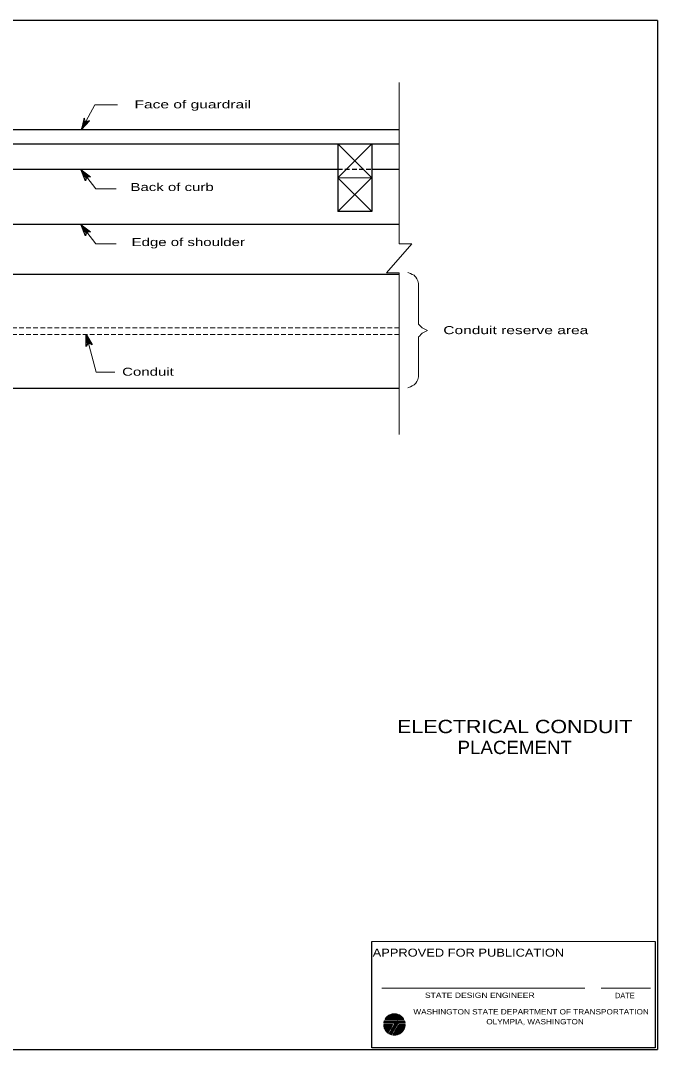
# Model space of a CAD drawing. Extents: x 993470 to 994006, y 1010815 to 1011161.
# Drawn here: x 993791.1 to 994005.6, y 1010814.9 to 1011161.5 of the extents above; entities that cross this region are included whole.
import ezdxf
from ezdxf.enums import TextEntityAlignment as Align

# ---------------------------------------------------------------- set-up
doc = ezdxf.new("R2010")
doc.units = 0
doc.header["$LTSCALE"] = 0.53
doc.linetypes.add('LONG_DASHED', pattern=[7.5, 6, -1.5])
doc.linetypes.add('MEDIUM_DASHED', pattern=[4.5, 3, -1.5])
for name, color, linetype, lineweight in [('1', 7, 'Continuous', 25), ('15', 7, 'Continuous', 13), ('16', 7, 'Continuous', 25), ('20', 7, 'Continuous', 13), ('30', 7, 'Continuous', 25), ('32', 7, 'Continuous', 25), ('63', 7, 'Continuous', 13)]:
    doc.layers.add(name, color=color, linetype=linetype, lineweight=lineweight)

msp = doc.modelspace()

# ---------------------------------------------------------------- linework, layer by layer
at = {"layer": '1'}
for p, q in [((993897.987, 1011119.934), (993897.987, 1011097.116)), ((993909.389, 1011119.934), (993909.389, 1011097.116)), ((993509.149, 1011076.054), (993918.64, 1011076.054))]:
    msp.add_line(p, q, dxfattribs=at)
at = {"layer": '1', "linetype": 'MEDIUM_DASHED', "lineweight": 13}
for p, q in [((993918.64, 1011058.023), (993727.094, 1011058.023)), ((993918.64, 1011055.697), (993727.094, 1011055.697))]:
    msp.add_line(p, q, dxfattribs=at)
at = {"layer": '1', "lineweight": 13}
for p, q in [((993909.389, 1010851.248), (994004.853, 1010851.248)), ((993912.843, 1010835.566), (993981.209, 1010835.566)), ((993986.617, 1010835.566), (994003.227, 1010835.566))]:
    msp.add_line(p, q, dxfattribs=at)
at = {"layer": '15'}
msp.add_lwpolyline([(993918.64, 1011086.217), (993922.874, 1011086.217), (993914.407, 1011076.455), (993918.64, 1011076.455)], dxfattribs=at)
at = {"layer": '15', "lineweight": 25}
msp.add_lwpolyline([(994004.853, 1010851.248), (994004.853, 1010815.474), (993909.389, 1010815.474), (993909.389, 1010851.248)], dxfattribs=at)
at = {"layer": '16'}
for points in [[(993812.819, 1011127.826), (993812.561, 1011128.654), (993811.649, 1011124.772), (993814.403, 1011127.654), (993813.575, 1011127.426), (993811.649, 1011124.772), (993812.819, 1011127.826), (993812.989, 1011127.254), (993813.575, 1011127.426)], [(993813.181, 1011108.364), (993813.053, 1011107.506), (993811.527, 1011111.188), (993814.709, 1011108.792), (993813.853, 1011108.892), (993811.527, 1011111.188), (993813.181, 1011108.364), (993813.253, 1011108.962), (993813.853, 1011108.892)], [(993813.181, 1011089.826), (993813.053, 1011088.968), (993811.527, 1011092.65), (993814.709, 1011090.254), (993813.853, 1011090.354), (993811.527, 1011092.65), (993813.181, 1011089.826), (993813.253, 1011090.424), (993813.853, 1011090.354)], [(993813.693, 1011052.443), (993813.235, 1011051.717), (993813.265, 1011055.697), (993815.263, 1011052.245), (993814.505, 1011052.673), (993813.265, 1011055.697), (993813.693, 1011052.443), (993813.993, 1011052.971), (993814.505, 1011052.673)]]:
    msp.add_lwpolyline(points, dxfattribs=at)
at = {"layer": '20'}
msp.add_lwpolyline([(993921.52, 1011076.579), (993922.44, 1011076.277), (993923.044, 1011075.975), (993923.662, 1011075.659), (993923.964, 1011075.357), (993924.266, 1011075.055), (993924.568, 1011074.437), (993924.884, 1011073.833), (993925.186, 1011072.913), (993925.186, 1011059.183), (993925.79, 1011058.564), (993926.408, 1011057.96), (993927.012, 1011057.644), (993928.234, 1011057.04), (993926.408, 1011056.12), (993926.092, 1011055.818), (993925.488, 1011055.2), (993925.186, 1011054.898), (993925.186, 1011041.47), (993924.884, 1011040.55), (993924.568, 1011039.946), (993924.266, 1011039.328), (993923.964, 1011039.026), (993923.662, 1011038.724), (993923.044, 1011038.408), (993922.44, 1011038.106), (993921.52, 1011037.804)], dxfattribs=at)
at = {"layer": '30'}
for p, q in [((994005.609, 1011161.474), (993469.979, 1011161.474)), ((994005.609, 1011161.474), (994005.609, 1010814.89)), ((993469.979, 1010814.89), (994005.609, 1010814.89))]:
    msp.add_line(p, q, dxfattribs=at)
at = {"layer": '32', "lineweight": 13}
for p, q in [((993918.64, 1011086.217), (993918.64, 1011140.582)), ((993897.987, 1011119.934), (993909.389, 1011108.504)), ((993898.001, 1011108.532), (993909.389, 1011119.934)), ((993816.479, 1011104.838), (993811.527, 1011111.188)), ((993909.375, 1011108.532), (993897.987, 1011108.546)), ((993897.987, 1011108.546), (993909.389, 1011097.116)), ((993897.987, 1011097.116), (993909.375, 1011108.532)), ((993816.479, 1011104.838), (993823.313, 1011104.838)), ((993816.479, 1011086.3), (993811.527, 1011092.65)), ((993816.479, 1011086.3), (993823.313, 1011086.3)), ((993918.64, 1011022.09), (993918.64, 1011076.455)), ((993816.646, 1011043.015), (993813.265, 1011055.697)), ((993816.646, 1011043.015), (993822.826, 1011043.015))]:
    msp.add_line(p, q, dxfattribs=at)
at = {"layer": '32'}
for p, q in [((993509.149, 1011124.772), (993918.64, 1011124.772)), ((993509.149, 1011119.934), (993918.64, 1011119.934)), ((993785.783, 1011111.458), (993897.987, 1011111.458)), ((993909.389, 1011111.458), (993918.64, 1011111.458)), ((993909.389, 1011097.116), (993897.987, 1011097.116)), ((993509.149, 1011092.92), (993918.64, 1011092.92)), ((993509.149, 1011037.654), (993918.64, 1011037.654))]:
    msp.add_line(p, q, dxfattribs=at)
at = {"layer": '32', "linetype": 'LONG_DASHED', "lineweight": 13}
msp.add_line((993909.389, 1011119.934), (993897.987, 1011119.934), dxfattribs=at)
at = {"layer": '32', "linetype": 'MEDIUM_DASHED'}
msp.add_line((993897.987, 1011111.458), (993909.389, 1011111.458), dxfattribs=at)
at = {"layer": '32', "lineweight": 13}
msp.add_lwpolyline([(993823.777, 1011133.062), (993816.143, 1011133.062), (993811.649, 1011124.772)], dxfattribs=at)
at = {"layer": '63'}
for points in [[(993920.191, 1010825.02), (993913.869, 1010825.02), (993913.927, 1010825.092), (993920.149, 1010825.092), (993920.091, 1010825.192), (993913.983, 1010825.192), (993914.027, 1010825.278), (993920.035, 1010825.278), (993919.991, 1010825.378), (993914.083, 1010825.378), (993914.141, 1010825.448), (993919.935, 1010825.448), (993919.849, 1010825.534), (993914.197, 1010825.534), (993914.283, 1010825.606), (993919.791, 1010825.606), (993919.691, 1010825.706), (993914.383, 1010825.706), (993914.427, 1010825.806), (993919.635, 1010825.806), (993919.535, 1010825.892), (993914.525, 1010825.892), (993914.611, 1010825.962), (993919.449, 1010825.962), (993919.363, 1010826.048), (993914.711, 1010826.048), (993914.811, 1010826.148), (993919.249, 1010826.148), (993919.149, 1010826.22), (993914.925, 1010826.22), (993915.069, 1010826.32), (993919.007, 1010826.32), (993918.863, 1010826.39), (993915.211, 1010826.39), (993915.367, 1010826.49), (993918.707, 1010826.49), (993918.535, 1010826.562), (993915.539, 1010826.562), (993915.739, 1010826.648), (993918.335, 1010826.648), (993918.079, 1010826.748), (993915.995, 1010826.748), (993916.323, 1010826.832), (993917.751, 1010826.832), (993917.565, 1010826.848), (993917.337, 1010826.89), (993917.037, 1010826.89), (993916.737, 1010826.89), (993916.495, 1010826.848), (993916.323, 1010826.832)], [(993913.927, 1010825.092), (993913.983, 1010825.192), (993914.027, 1010825.278), (993914.083, 1010825.378), (993914.141, 1010825.448), (993914.197, 1010825.534), (993914.283, 1010825.606), (993914.383, 1010825.706), (993914.427, 1010825.806), (993914.525, 1010825.892), (993914.611, 1010825.962), (993914.711, 1010826.048), (993914.811, 1010826.148), (993914.925, 1010826.22), (993915.069, 1010826.32), (993915.211, 1010826.39), (993915.367, 1010826.49), (993915.539, 1010826.562), (993915.739, 1010826.648), (993915.995, 1010826.748)], [(993917.751, 1010826.832), (993918.079, 1010826.748), (993918.335, 1010826.648), (993918.535, 1010826.562), (993918.707, 1010826.49), (993918.863, 1010826.39), (993919.007, 1010826.32), (993919.149, 1010826.22), (993919.249, 1010826.148), (993919.363, 1010826.048), (993919.449, 1010825.962), (993919.535, 1010825.892), (993919.635, 1010825.806), (993919.691, 1010825.706), (993919.791, 1010825.606), (993919.849, 1010825.534), (993919.935, 1010825.448), (993919.991, 1010825.378), (993920.035, 1010825.278), (993920.091, 1010825.192), (993920.149, 1010825.092), (993920.191, 1010825.02)], [(993913.469, 1010823.95), (993920.591, 1010823.95), (993920.605, 1010823.85), (993913.469, 1010823.85), (993913.441, 1010823.78), (993920.605, 1010823.78), (993918.707, 1010823.78), (993918.621, 1010823.736), (993918.421, 1010823.68), (993917.081, 1010823.68), (993917.137, 1010823.594), (993918.265, 1010823.594), (993918.165, 1010823.536), (993918.137, 1010823.508), (993917.137, 1010823.508), (993917.137, 1010823.48), (993917.123, 1010823.422), (993918.065, 1010823.422), (993918.023, 1010823.366), (993917.979, 1010823.352), (993917.037, 1010823.352), (993916.995, 1010823.252), (993917.951, 1010823.252), (993917.907, 1010823.166), (993916.967, 1010823.166), (993916.895, 1010823.066), (993917.851, 1010823.066), (993917.807, 1010822.994), (993916.837, 1010822.994), (993916.781, 1010822.894), (993917.751, 1010822.894), (993917.693, 1010822.838), (993916.737, 1010822.838), (993916.709, 1010822.738), (993917.651, 1010822.738), (993917.609, 1010822.652), (993916.667, 1010822.652), (993916.581, 1010822.552), (993917.537, 1010822.552), (993917.495, 1010822.452), (993916.553, 1010822.452), (993916.509, 1010822.38), (993917.451, 1010822.38), (993917.395, 1010822.296), (993916.453, 1010822.296), (993916.395, 1010822.224), (993917.351, 1010822.224), (993917.295, 1010822.124), (993916.353, 1010822.124), (993916.295, 1010822.038), (993917.237, 1010822.038), (993917.195, 1010821.952), (993916.253, 1010821.952), (993916.209, 1010821.868), (993917.151, 1010821.868), (993917.081, 1010821.796), (993916.153, 1010821.796), (993916.095, 1010821.71), (993917.037, 1010821.71), (993916.995, 1010821.61), (993916.053, 1010821.61), (993915.995, 1010821.538), (993916.937, 1010821.538), (993916.895, 1010821.438), (993915.953, 1010821.438), (993915.895, 1010821.354), (993916.837, 1010821.34), (993916.781, 1010821.254), (993915.853, 1010821.254), (993915.795, 1010821.182), (993916.737, 1010821.182), (993916.709, 1010821.096), (993915.739, 1010821.096), (993915.697, 1010820.996), (993916.653, 1010820.996), (993916.581, 1010820.926), (993915.667, 1010820.926), (993915.597, 1010820.826), (993916.553, 1010820.826), (993916.495, 1010820.74), (993915.567, 1010820.74), (993915.511, 1010820.668), (993916.453, 1010820.668), (993916.395, 1010820.582), (993915.439, 1010820.582), (993915.411, 1010820.482), (993916.353, 1010820.482), (993916.295, 1010820.412), (993915.325, 1010820.412), (993915.283, 1010820.312), (993916.253, 1010820.312), (993916.195, 1010820.24), (993915.253, 1010820.24), (993915.211, 1010820.198), (993915.311, 1010820.14), (993916.153, 1010820.14), (993916.095, 1010820.054), (993915.511, 1010820.054), (993915.667, 1010819.954), (993916.053, 1010819.954), (993915.995, 1010819.884)], [(993913.441, 1010823.308), (993916.295, 1010823.308), (993916.367, 1010823.28), (993916.395, 1010823.252), (993916.409, 1010823.208), (993913.441, 1010823.208), (993913.441, 1010823.108), (993916.409, 1010823.108), (993916.367, 1010823.022), (993913.441, 1010823.022), (993913.441, 1010822.952), (993916.323, 1010822.952), (993916.295, 1010822.866), (993913.469, 1010822.866), (993913.469, 1010822.78), (993916.239, 1010822.78), (993916.167, 1010822.694), (993913.499, 1010822.694), (993913.513, 1010822.624), (993916.109, 1010822.624), (993916.081, 1010822.524), (993913.541, 1010822.524), (993913.541, 1010822.438), (993916.039, 1010822.438), (993915.953, 1010822.338), (993913.555, 1010822.338), (993913.599, 1010822.28), (993915.911, 1010822.28), (993915.881, 1010822.18), (993913.613, 1010822.18), (993913.627, 1010822.082), (993915.839, 1010822.082), (993915.781, 1010821.982), (993913.669, 1010821.982), (993913.713, 1010821.91), (993915.725, 1010821.924), (993915.667, 1010821.824), (993913.755, 1010821.824), (993913.783, 1010821.752), (993915.625, 1010821.752), (993915.581, 1010821.652), (993913.827, 1010821.652), (993913.869, 1010821.568), (993915.511, 1010821.568), (993915.467, 1010821.496), (993913.927, 1010821.496), (993913.983, 1010821.396), (993915.425, 1010821.396), (993915.367, 1010821.31), (993914.027, 1010821.31), (993914.083, 1010821.24), (993915.325, 1010821.24), (993915.267, 1010821.14), (993914.141, 1010821.14), (993914.227, 1010821.04), (993915.211, 1010821.04), (993915.169, 1010820.968), (993914.297, 1010820.968), (993914.383, 1010820.868), (993915.111, 1010820.868), (993915.069, 1010820.812), (993914.455, 1010820.812), (993914.541, 1010820.712), (993915.011, 1010820.712), (993914.969, 1010820.626), (993914.641, 1010820.626), (993914.711, 1010820.526), (993914.911, 1010820.526), (993914.869, 1010820.412), (993914.711, 1010820.526)], [(993913.441, 1010823.308), (993913.441, 1010823.208), (993913.441, 1010823.108), (993913.441, 1010823.022), (993913.441, 1010822.952), (993913.469, 1010822.866), (993913.469, 1010822.78), (993913.499, 1010822.694), (993913.513, 1010822.624), (993913.541, 1010822.524), (993913.541, 1010822.438), (993913.555, 1010822.338), (993913.599, 1010822.28), (993913.613, 1010822.18), (993913.627, 1010822.082), (993913.669, 1010821.982), (993913.755, 1010821.824), (993913.783, 1010821.752), (993913.827, 1010821.652), (993913.869, 1010821.568), (993913.927, 1010821.496), (993913.983, 1010821.396), (993914.027, 1010821.31), (993914.083, 1010821.24), (993914.141, 1010821.14), (993914.227, 1010821.04), (993914.297, 1010820.968), (993914.383, 1010820.868), (993914.455, 1010820.812), (993914.541, 1010820.712), (993914.641, 1010820.626), (993914.711, 1010820.526), (993914.911, 1010820.526), (993914.969, 1010820.626), (993915.011, 1010820.712), (993916.409, 1010823.108), (993916.409, 1010823.166), (993916.409, 1010823.208)], [(993913.627, 1010824.55), (993913.613, 1010824.464), (993913.599, 1010824.364), (993913.555, 1010824.292), (993913.541, 1010824.194), (993913.513, 1010824.108), (993913.499, 1010824.008), (993913.469, 1010823.95), (993913.469, 1010823.85)], [(993913.627, 1010824.55), (993917.665, 1010824.55), (993917.751, 1010824.522), (993917.793, 1010824.492), (993917.807, 1010824.464), (993913.613, 1010824.464), (993913.599, 1010824.364), (993917.865, 1010824.364), (993917.865, 1010824.336), (993917.865, 1010824.308), (993917.865, 1010824.292), (993913.555, 1010824.292), (993913.541, 1010824.194), (993917.865, 1010824.194), (993917.823, 1010824.108), (993913.513, 1010824.108), (993913.499, 1010824.008), (993920.563, 1010824.008), (993920.547, 1010824.108), (993917.823, 1010824.108), (993917.865, 1010824.194), (993920.519, 1010824.194), (993920.505, 1010824.292), (993917.951, 1010824.292), (993918.065, 1010824.364), (993920.491, 1010824.392), (993920.447, 1010824.464), (993918.207, 1010824.464), (993918.265, 1010824.492), (993918.321, 1010824.522), (993918.465, 1010824.55), (993920.433, 1010824.55), (993920.447, 1010824.464)], [(993916.967, 1010823.78), (993917.081, 1010823.68), (993917.137, 1010823.594), (993917.137, 1010823.508), (993917.123, 1010823.422), (993917.037, 1010823.352), (993915.253, 1010820.24), (993915.311, 1010820.14), (993915.511, 1010820.054)], [(993918.421, 1010823.68), (993918.321, 1010823.636), (993918.265, 1010823.594), (993918.137, 1010823.508), (993918.065, 1010823.422), (993917.979, 1010823.352), (993917.951, 1010823.252), (993917.907, 1010823.166), (993917.851, 1010823.066), (993917.807, 1010822.994), (993917.751, 1010822.894), (993917.693, 1010822.838), (993917.651, 1010822.738), (993917.609, 1010822.652), (993917.537, 1010822.552), (993917.495, 1010822.452), (993915.995, 1010819.854)], [(993920.619, 1010823.28), (993920.619, 1010823.208), (993920.619, 1010823.108), (993920.619, 1010823.022), (993920.619, 1010822.952), (993920.605, 1010822.852), (993920.591, 1010822.752), (993920.591, 1010822.694), (993920.563, 1010822.624), (993920.547, 1010822.524), (993920.519, 1010822.424), (993920.505, 1010822.324), (993920.463, 1010822.266), (993920.447, 1010822.166), (993920.433, 1010822.082), (993920.391, 1010821.982), (993920.347, 1010821.91), (993920.305, 1010821.824), (993920.291, 1010821.724), (993920.233, 1010821.624), (993920.191, 1010821.568), (993920.133, 1010821.496), (993920.091, 1010821.396), (993920.019, 1010821.296), (993919.949, 1010821.196), (993919.891, 1010821.14), (993919.835, 1010821.04), (993919.777, 1010820.968), (993919.691, 1010820.868), (993919.605, 1010820.782), (993919.521, 1010820.712), (993919.421, 1010820.612), (993919.321, 1010820.526), (993919.207, 1010820.454), (993919.107, 1010820.354), (993918.949, 1010820.254), (993918.807, 1010820.168), (993918.649, 1010820.098), (993918.479, 1010820.012), (993918.265, 1010819.912), (993917.979, 1010819.84), (993917.565, 1010819.74), (993916.453, 1010819.74), (993916.495, 1010819.84), (993918.293, 1010822.952), (993918.365, 1010823.022), (993918.465, 1010823.108), (993918.593, 1010823.208)], [(993920.619, 1010823.28), (993918.863, 1010823.28), (993918.749, 1010823.252), (993918.649, 1010823.222), (993918.593, 1010823.208), (993920.619, 1010823.208), (993920.619, 1010823.108), (993918.465, 1010823.108), (993918.393, 1010823.052), (993918.365, 1010823.022), (993920.619, 1010823.022), (993920.619, 1010822.952), (993918.293, 1010822.952), (993918.237, 1010822.852), (993920.605, 1010822.852), (993920.591, 1010822.752), (993918.207, 1010822.752), (993918.121, 1010822.694), (993920.591, 1010822.694), (993920.563, 1010822.624), (993918.079, 1010822.624), (993918.023, 1010822.524), (993920.547, 1010822.524), (993920.519, 1010822.424), (993917.979, 1010822.424), (993917.923, 1010822.324), (993920.505, 1010822.324), (993920.463, 1010822.266), (993917.879, 1010822.266), (993917.823, 1010822.166), (993920.447, 1010822.166), (993920.433, 1010822.082), (993917.793, 1010822.082), (993917.751, 1010821.982), (993920.391, 1010821.982), (993920.347, 1010821.91), (993917.693, 1010821.91), (993917.637, 1010821.824), (993920.305, 1010821.824), (993920.291, 1010821.724), (993917.565, 1010821.724), (993917.537, 1010821.624), (993920.233, 1010821.624), (993920.191, 1010821.568), (993917.479, 1010821.568), (993917.437, 1010821.496), (993920.133, 1010821.496), (993920.091, 1010821.396), (993917.379, 1010821.396), (993917.337, 1010821.296), (993920.019, 1010821.296), (993919.949, 1010821.196), (993917.295, 1010821.224), (993917.237, 1010821.14), (993919.891, 1010821.14), (993919.835, 1010821.04), (993917.181, 1010821.04), (993917.137, 1010820.968), (993919.777, 1010820.968), (993919.691, 1010820.868), (993917.081, 1010820.868), (993917.037, 1010820.782), (993919.605, 1010820.782), (993919.521, 1010820.712), (993916.981, 1010820.712), (993916.937, 1010820.612), (993919.421, 1010820.612), (993919.321, 1010820.526), (993916.881, 1010820.526), (993916.837, 1010820.454), (993919.207, 1010820.454), (993919.107, 1010820.354), (993916.781, 1010820.354), (993916.737, 1010820.254)], [(993917.807, 1010824.464), (993917.823, 1010824.408), (993917.865, 1010824.364), (993917.865, 1010824.336), (993917.865, 1010824.292), (993917.865, 1010824.236), (993917.865, 1010824.194)], [(993918.023, 1010824.806), (993918.023, 1010824.82), (993918.023, 1010824.864), (993918.023, 1010824.878), (993918.023, 1010824.878), (993918.023, 1010824.906), (993917.979, 1010824.92), (993917.979, 1010824.936), (993917.965, 1010824.964), (993917.923, 1010824.978), (993917.865, 1010825.02)], [(993918.207, 1010824.464), (993918.065, 1010824.364), (993917.951, 1010824.292), (993917.865, 1010824.194)], [(993918.421, 1010825.02), (993918.265, 1010824.978), (993917.923, 1010824.978), (993917.965, 1010824.964), (993918.207, 1010824.964), (993918.137, 1010824.92), (993917.979, 1010824.92), (993918.023, 1010824.906), (993918.107, 1010824.906), (993918.079, 1010824.878), (993918.023, 1010824.878), (993918.023, 1010824.864), (993918.065, 1010824.864), (993918.023, 1010824.806), (993918.023, 1010824.806), (993917.979, 1010824.778), (993918.023, 1010824.806)], [(993918.265, 1010824.978), (993918.221, 1010824.978), (993918.207, 1010824.964), (993918.137, 1010824.92), (993918.107, 1010824.906), (993918.079, 1010824.878), (993918.065, 1010824.864)], [(993920.605, 1010823.78), (993920.605, 1010823.85), (993920.591, 1010823.95), (993920.563, 1010824.008), (993920.547, 1010824.108), (993920.519, 1010824.194), (993920.505, 1010824.292), (993920.491, 1010824.392)], [(993915.995, 1010819.884), (993915.895, 1010819.884), (993915.995, 1010819.854), (993915.667, 1010819.954)], [(993916.737, 1010820.254), (993918.949, 1010820.254), (993918.807, 1010820.168), (993916.681, 1010820.198), (993916.653, 1010820.098), (993918.649, 1010820.098), (993918.479, 1010820.012), (993916.581, 1010820.012), (993916.553, 1010819.912), (993918.265, 1010819.912), (993918.107, 1010819.854), (993917.979, 1010819.84), (993916.495, 1010819.84), (993916.453, 1010819.74), (993916.453, 1010819.74), (993917.565, 1010819.74), (993917.351, 1010819.726), (993917.023, 1010819.698), (993916.709, 1010819.726), (993916.453, 1010819.74)]]:
    msp.add_lwpolyline(points, dxfattribs=at)

# ---------------------------------------------------------------- texts
at = {"layer": '20'}
for s, width, p in [('Face of guardrail', 1.45, (993849.129, 1011131.906)), ('Back of curb', 1.4, (993842.166, 1011104.054)), ('Edge of shoulder', 1.4, (993847.606, 1011085.516)), ('Conduit reserve area', 1.45, (993957.919, 1011055.839)), ('Conduit', 1.4, (993834.044, 1011041.836))]:
    msp.add_text(s, height=2.697, dxfattribs=dict(at, width=width)).set_placement(p, align=Align.CENTER)
at = {"layer": '32'}
for s, height, width, p in [('ELECTRICAL CONDUIT', 4.488, 1.2, (993957.562, 1010921.428)), ('PLACEMENT', 4.488, 1.05, (993957.559, 1010914.392)), ('STATE DESIGN ENGINEER', 1.795, 1.2, (993945.787, 1010832.242)), ('WASHINGTON STATE DEPARTMENT OF TRANSPORTATION', 1.795, 1.15, (993963.072, 1010826.676)), ('OLYMPIA, WASHINGTON', 1.795, 1.15, (993964.4, 1010823.336))]:
    msp.add_text(s, height=height, dxfattribs=dict(at, width=width)).set_placement(p, align=Align.CENTER)
at = {"layer": '32', "width": 1.2}
msp.add_text('APPROVED FOR PUBLICATION', height=2.699, dxfattribs=at).set_placement((993974.209, 1010846.14), align=Align.RIGHT)
at = {"layer": '32'}
msp.add_text('DATE', height=1.8, dxfattribs=at).set_placement((993997.957, 1010832.156), align=Align.RIGHT)

doc.saveas('drawing.dxf')
